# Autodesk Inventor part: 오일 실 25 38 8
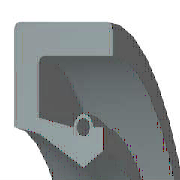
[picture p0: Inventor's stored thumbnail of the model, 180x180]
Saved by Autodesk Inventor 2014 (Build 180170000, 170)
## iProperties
IsCustomPart: 1
Created: 2012-02
Part Number: 오일 실 25 38 8
Material: 고무
Description: 오일-실
Document SubType Name: Modeling
Standard: KS B 2804
Designer: mduedu
Standards Organization: KS
Language: ko-KR
Size Designation: S - 25 38 8
Categories: <MemberInstance><Categories><Category DisplayName="샤프트 부품" InternalName="7f7aeb1f-a693-4053-b835-cee3144e0d98" Mnemonic="SHFT"><Category DisplayName="실링" Intern
Density: 0.93 g/cm^3
Appearance: Rubber - Black - Version 1.1
Author: mduedu
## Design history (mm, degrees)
revolve "본체" stored, may be unused: angle "d17" = 90 deg
revolve "스프링1" stored, may be unused: angle "d18" = 90 deg
body "Solid1"
sketch "스케치1"
  geometry: L1 (0, 19)-(8, 19); L2 (8, 19)-(8, 17.75); L3 (8, 17.75)-(1.75, 17.75); L4 (0, 19)-(0, 14.6); L5 (0, 14.6)-(1.75, 14.25); L6 (1.75, 14.25)-(4.9, 12.5); L7 (4.9, 12.5)-(0, 12.5); L8 (6.3, 13.375)-(6.3, 14.6); L9 (0, 0)-(9.586, 0) reference; L10 (4.9, 12.5)-(6.3, 13.375); L11 (0, 18)-(0, -3) reference; L12 (-1.917, 0)-(11.503, 0) reference; L13 (4.2, 14.6)-(1.75, 15.09); L14 (1.75, 15.09)-(1.75, 17.75); L15 (6.3, 14.6)-(5.6, 14.6); C1 r 0.455 at (4.9, 14.6); A1 r 0.7 centre (4.9, 14.6) between (5.6, 14.6) and (4.2, 14.6)
  constraints: 26 end point, 5 horizontal alignment, 4 perpendicular, 2 centre point, 2 collinear, 2 horizontal, 2 parallel, 2 point on circle, 2 point on line, 2 vertical alignment, 1 coincident
  dimensions: "d0" = 38 diameter of L1 L9 (= SD2); "d1" = 26.75 diameter of L8.start L9 (= ABDM); "d2" = 1.25 distance of L1.end L2.end (computed from SD); "d3" = 0.91 diameter of C1 (= SPDI); "d4" = 1.4 diameter of A1 (= SPDA); "d5" = 25 diameter of L6.end L9 (= NND); "d6" = 28.5 diameter of L5.end L9 (= TKDM); "d7" = 29.2 diameter of L4.end L9 (= HLDM); "d8" = 4.9 distance from line of C1.centre L4 (= SPDST); "d9" = 6.3 distance between parallel lines of L8 L4 (= SDI); "d10" = 8 distance between parallel lines of L2 L4 (= SWDT); "d12" = 1.75 distance between parallel lines of L14 L4 (= SD)
fillet "모깎기1" dims "d11" = 0.5 (= RR)
other parameters: "SD2" = 38 [user parameter; used in 1 equation term], "SWDT" = 8 [user parameter; used in 1 equation term], "RR" = 0.5 [user parameter; used in 1 equation term], "SD" = 1.75 [user parameter; used in 2 equation terms], "NND" = 25 [user parameter; used in 1 equation term], "SPDA" = 1.4 [user parameter; used in 1 equation term], "SPDI" = 0.91 [user parameter; used in 1 equation term], "TKDM" = 28.5 [user parameter; used in 1 equation term], "HLDM" = 29.2 [user parameter; used in 1 equation term], "ABDM" = 26.75 [user parameter; used in 1 equation term], "SDI" = 6.3 [user parameter; used in 1 equation term], "SPDST" = 4.9 [user parameter; used in 1 equation term], "d13" = 0, "d14" = 0, "d15" = 0, "LAB" = 0.35 [user parameter]
